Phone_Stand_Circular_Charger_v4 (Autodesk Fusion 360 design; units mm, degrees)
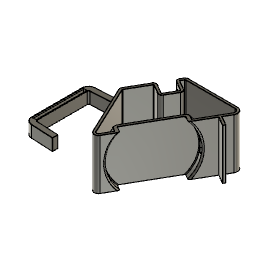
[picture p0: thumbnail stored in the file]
sketch "Sketch1" plane through (0, 0, 0) normal (0, 1, 0) x axis (1, 0, 0)
  line L1 (-76.7719, -132.9728) -> (-6.9282, -12)
  line L2 (120, 0) -> (0, 0)
  line L3 (-120.3527, -62.762) -> (-87.3932, -132.5355)
  line L4 (-13.8564, 0) -> (-83.7158, 0)
  line L5 (-31.1769, -36) -> (-25.1147, -39.5)
  line L6 (-82.0429, -122.1025) -> (-32.5429, -36.366)
  line L7 (-75.6147, -126.9686) -> (-81.6769, -123.4686)
  line L8 (-76.7719, -132.9728) -> (-74.8827, -129.7006)
  line L9 (-6.9282, -12) -> (-22.3827, -38.7679)
  line L10 (-0.1423, -30.2465) -> (-13.1327, -22.7465)
  line L11 (-1.8923, -33.2776) -> (-0.1423, -30.2465)
  line L12 (-14.8827, -25.7776) -> (-1.8923, -33.2776)
  line L13 (-88.0459, -2.5) -> (-120.1618, -58.1264)
  line L14 (-75.9216, -19.5) -> (-88.9119, -12)
  line L15 (-84.5555, -36.4545) -> (-75.5555, -20.866)
  line L16 (-98.9119, -29.3205) -> (-85.9216, -36.8205)
  line L17 (-120.1618, -58.1264) -> (-104.376, -30.7846)
  line L18 (-88.0459, -2.5) -> (-90.376, -6.5359)
  line L19 (-9.9593, -10.25) -> (-24.6638, -35.7189)
  line L20 (-13.8564, -3.5) -> (-83.7158, -3.5)
  line L21 (-85.0148, -4.25) -> (-87.345, -8.2859)
  line L22 (-74.1716, -16.4689) -> (-87.1619, -8.9689)
  line L23 (-81.5244, -38.2045) -> (-72.5244, -22.616)
  line L24 (-100.6619, -32.3516) -> (-87.6716, -39.8516)
  line L25 (-117.1307, -59.8764) -> (-101.345, -32.5346)
  line L26 (-117.188, -61.267) -> (-84.2285, -131.0406)
  line L27 (-79.803, -131.2228) -> (-78.6638, -129.2497)
  line L28 (-78.6638, -129.2497) -> (-83.4269, -126.4997)
  line L29 (-85.074, -120.3525) -> (-35.574, -34.616)
  line L30 (-29.4269, -32.9689) -> (-24.6638, -35.7189)
  line L31 (-24.6638, -35.7189) -> (-78.6638, -129.2497)
  arc A1 centre (-13.8564, -8) radius 8 clockwise from (-13.8564, 0) to (-6.9282, -12)
  arc A2 centre (-81.968, -129.9728) radius 6 clockwise from (-76.7719, -132.9728) to (-87.3932, -132.5355)
  arc A3 centre (-76.6147, -128.7006) radius 2 clockwise from (-75.6147, -126.9686) to (-74.8827, -129.7006)
  arc A4 centre (-24.1147, -37.7679) radius 2 clockwise from (-22.3827, -38.7679) to (-25.1147, -39.5)
  arc A5 centre (-81.1769, -122.6025) radius 1 clockwise from (-81.6769, -123.4686) to (-82.0429, -122.1025)
  arc A6 centre (-31.6769, -36.866) radius 1 clockwise from (-32.5429, -36.366) to (-31.1769, -36)
  arc A7 centre (-115.8317, -60.6264) radius 5 clockwise from (-120.3527, -62.762) to (-120.1618, -58.1264)
  arc A8 centre (-83.7158, -5) radius 5 clockwise from (-88.0459, -2.5) to (-83.7158, 0)
  arc A9 centre (-86.9119, -8.5359) radius 4 clockwise from (-88.9119, -12) to (-90.376, -6.5359)
  arc A10 centre (-100.9119, -32.7846) radius 4 clockwise from (-104.376, -30.7846) to (-98.9119, -29.3205)
  arc A11 centre (-85.4216, -35.9545) radius 1 clockwise from (-84.5555, -36.4545) to (-85.9216, -36.8205)
  arc A12 centre (-76.4216, -20.366) radius 1 clockwise from (-75.9216, -19.5) to (-75.5555, -20.866)
  arc A13 centre (-13.8564, -8) radius 4.5 clockwise from (-13.8564, -3.5) to (-9.9593, -10.25)
  arc A14 centre (-83.7158, -5) radius 1.5 clockwise from (-85.0148, -4.25) to (-83.7158, -3.5)
  arc A15 centre (-86.9119, -8.5359) radius 0.5 clockwise from (-87.1619, -8.9689) to (-87.345, -8.2859)
  arc A16 centre (-76.4216, -20.366) radius 4.5 clockwise from (-74.1716, -16.4689) to (-72.5244, -22.616)
  arc A17 centre (-85.4216, -35.9545) radius 4.5 clockwise from (-81.5244, -38.2045) to (-87.6716, -39.8516)
  arc A18 centre (-100.9119, -32.7846) radius 0.5 clockwise from (-101.345, -32.5346) to (-100.6619, -32.3516)
  arc A19 centre (-115.8317, -60.6264) radius 1.5 clockwise from (-117.188, -61.267) to (-117.1307, -59.8764)
  arc A20 centre (-81.968, -129.9728) radius 2.5 clockwise from (-79.803, -131.2228) to (-84.2285, -131.0406)
  arc A21 centre (-81.1769, -122.6025) radius 4.5 clockwise from (-83.4269, -126.4997) to (-85.074, -120.3525)
  arc A22 centre (-31.6769, -36.866) radius 4.5 clockwise from (-35.574, -34.616) to (-29.4269, -32.9689)
  point P1 (0, 0)
  point P2 (0, 0)
  point P6 (0, 0)
  point P7 (-23.3827, -40.5)
  point P5 (-150, 0)
  point P3 (-82.5, -142.8942)
  point P22 (-13.1327, -22.7465)
  point P9 (-82.5429, -122.9686)
  point P8 (-32.0429, -35.5)
  point P25 (-14.8827, -25.7776)
  point P38 (-92.376, -10)
  point P83 (-57.2929, -79.2343)
  point P23 (-0.1423, -30.2465)
  point P24 (-1.8923, -33.2776)
  horizontal L2
  coincident P1 P2
  coincident P1 P6
  parallel L2 L4
  coincident L1 P7
  perpendicular L1 L5
  perpendicular L5 L6
  perpendicular L1 L7
  coincident P5 L3
  coincident P5 L4
  coincident P2 L1
  coincident P6 L4
  tangent L1 A1
  tangent L4 A1
  coincident P3 L3
  coincident P3 L1
  tangent L3 A2
  tangent L1 A2
  tangent L7 A3
  tangent L8 A3
  parallel L1 L8
  coincident P7 L5
  coincident P7 L9
  tangent L5 A4
  tangent L9 A4
  coincident L9 P22
  perpendicular L9 L10
  perpendicular L10 L11
  parallel L10 L12
  coincident P9 L6
  coincident P9 L7
  tangent L6 A5
  tangent L7 A5
  coincident P8 L5
  coincident P8 L6
  tangent L5 A6
  tangent L6 A6
  coincident L1 P25
  parallel L1 L13
  tangent L13 A7
  tangent L3 A7
  tangent L4 A8
  tangent L13 A8
  coincident L13 P38
  perpendicular L13 L14
  perpendicular L14 L15
  perpendicular L13 L16
  coincident P38 L18
  coincident P38 L14
  tangent L18 A9
  tangent L14 A9
  tangent L16 A10
  tangent L17 A10
  parallel L13 L17
  tangent L16 A11
  tangent L15 A11
  tangent L14 A12
  tangent L15 A12
  equal A11 A12
  midpoint L6 P83
  dimension "d34_1" angle L1 L2 = 120
  dimension "d35_1" distance P2 P3 = 165
  dimension "d36_1" distance P5 P6 = 150
  dimension "d37_1" distance P7 P8 = 10
  dimension "d38_1" distance P6 P7 = 40.5
  dimension "d39_1" distance P8 P9 = 101
  dimension "d41_1" radius A1 = 8
  dimension "d42_1" radius A2 = 6
  dimension "d43_1" radius A3 = 2
  dimension "d44_1" radius A4 = 2
  dimension "d45_1" distance P23 P24 = 3.5
  dimension "d46_1" distance P22 P23 = 15
  dimension "d47_1" distance L5 L12 = 17
  dimension "d48_1" radius A5 = 1
  dimension "d49_1" radius A6 = 1
  dimension "d71_1" distance L1 L13 = 75
  dimension "d72_1" radius A7 = 5
  dimension "d73_1" radius A8 = 5
  dimension "d74_1" distance L14 L16 = 20
  dimension "d75_1" distance L13 L15 = 20
  dimension "d76_1" distance P2 P38 = 10
  dimension "d77_1" radius A9 = 4
  dimension "d78_1" radius A10 = 4
  dimension "d79_1" radius A11 = 1
  dimension "d80_1" = 3.5
extrude "Extrude1" new body sketch "Sketch1" profile of L1 L3 L4 L5 L7 A1 A2 L8 A3 L9 A4 L10 L11 L12 L13 A7 A8 L14 L15 L16 L17 L18 A9 A10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 along normal blind 72 named "d51_1"
work_plane "WorkPlane2"
sketch "Sketch9" plane through (-58.3067, 36, 68.0585) normal (0, -1, 0) x axis (1, 0, 0)
  line L1 (27.1298, -32.0585) -> (33.192, -28.5585)
  line L2 (-23.7362, 54.044) -> (25.7638, -31.6925)
  line L3 (28.8798, -35.0896) -> (33.6429, -32.3396)
  line L4 (-26.7673, 52.294) -> (22.7327, -33.4425)
  line L5 (-20.3571, 61.1911) -> (-25.1202, 58.4411)
  line L6 (-17.308, 58.91) -> (-23.3702, 55.41)
  line L7 (35.924, -29.2906) -> (-16.576, 61.6421)
  line L8 (9.674, 16.1757) -> (1.0138, 11.1757)
  line L9 (-2.0173, 9.4257) -> (1.0138, 11.1757)
  line L10 (-18.6071, 58.16) -> (-20.3571, 61.1911)
  line L11 (33.6429, -32.3396) -> (31.8929, -29.3085)
  arc A1 centre (34.192, -30.2906) radius 2 clockwise from (33.192, -28.5585) to (35.924, -29.2906)
  arc A2 centre (26.6298, -31.1925) radius 1 clockwise from (27.1298, -32.0585) to (25.7638, -31.6925)
  arc A3 centre (26.6298, -31.1925) radius 4.5 clockwise from (28.8798, -35.0896) to (22.7327, -33.4425)
  arc A4 centre (-22.8702, 54.544) radius 4.5 clockwise from (-26.7673, 52.294) to (-25.1202, 58.4411)
  arc A5 centre (-22.8702, 54.544) radius 1 clockwise from (-23.7362, 54.044) to (-23.3702, 55.41)
  arc A6 centre (-18.308, 60.6421) radius 2 clockwise from (-16.576, 61.6421) to (-17.308, 58.91)
  point P31 (-16.576, 61.6421)
  point P33 (-16.576, 61.6421)
  point P5 (35.924, -29.2906)
  point P34 (35.924, -29.2906)
  point P2 (1.0138, 11.1757)
  point P35 (1.0138, 11.1757)
  point P36 (9.674, 16.1757)
  point P37 (-2.0173, 9.4257)
  point P24 (-20.3571, 61.1911)
  point P38 (-20.3571, 61.1911)
  point P39 (-18.6071, 58.16)
  point P40 (31.8929, -29.3085)
  point P13 (33.6429, -32.3396)
  point P41 (33.6429, -32.3396)
  coincident P31 P33
  coincident P5 P34
  coincident P2 P35
  midpoint L7 P36
  midpoint L4 P37
  coincident P24 P38
  coincident L6 P39
  perpendicular L6 L10
  coincident L1 P40
  coincident P13 P41
  perpendicular L3 L11
revolve "Revolve1" sketch "Sketch9" AlongAngle 360
revolve "Revolve2" sketch "Sketch9" AlongAngle 360
split "Split3"
split "Split4"
work_plane "WorkPlane3" RotateAngle 0
sketch "Sketch2" plane through (-23.3827, 0, 40.5) normal (-0.5, 0, 0.866) x axis (0, 1, 0)
  line L1 (0, 2) -> (0, 9)
  line L2 (72, 2) -> (0, 2)
  line L3 (72, 9) -> (72, 2)
  line L4 (0, 9) -> (72, 9)
  line L5 (36, 9) -> (36, 2)
  line L6 (41, 1.8) -> (31, 1.8)
  line L7 (41, 9.3) -> (41, 1.8)
  line L8 (31, 9.3) -> (41, 9.3)
  line L9 (31, 1.8) -> (31, 9.3)
  line L10 (0, 0) -> (72, 0)
  arc A1 centre (41, 5.55) radius 3.75 clockwise from (41, 9.3) to (41, 1.8)
  arc A2 centre (31, 5.55) radius 3.75 clockwise from (31, 1.8) to (31, 9.3)
  point P6 (36, 2)
  point P7 (36, 9)
  point P12 (41, 5.55)
  point P14 (31, 5.55)
  point P8 (31, 1.8)
  point P9 (41, 1.8)
  point P11 (31, 9.3)
  midpoint L2 P6
  midpoint L4 P7
  horizontal L6
  vertical L7
  horizontal L8
  vertical L9
  midpoint L7 P12
  midpoint L9 P14
  dimension "d53_1" distance P8 P9 = 10
  dimension "d54_1" distance P8 P11 = 7.5
  dimension "d55_1" distance L5 L7 = 5
  dimension "d81_1" distance L6 L10 = 1.8
extrude "Extrude2" cut sketch "Sketch2" profile of L2 L4 L5 L6 L7 L8 L9 A1 A2 against normal blind 25 named "d56_1" and along normal blind 4.796
combine "Combine1"
fillet "Fillet1" radius 3.139 named "d58_1"
fillet "Fillet2" radius 0.5 named "d59_1"
fillet "Fillet3" radius 0.2
sketch "Sketch5" plane through (-27.4241, 0, 47.5) normal (-0.5, 0, 0.866) x axis (0, -1, 0)
  line L1 (0, -71) -> (-72, -71)
  line L2 (-72, -56) -> (0, -56)
  line L3 (-72, -71.5) -> (0, -71.5)
  line L4 (-36, -71.5) -> (-36, -56)
  line L5 (-46, -70.75) -> (-26, -70.75)
  line L6 (-46, -56.75) -> (-46, -70.75)
  line L7 (-26, -56.75) -> (-46, -56.75)
  line L8 (-26, -70.75) -> (-26, -56.75)
  line L9 (-46, -56.75) -> (-26, -70.75)
  line L10 (-26, -56.75) -> (-46, -70.75)
  line L11 (0, -56) -> (0, -71)
  line L12 (-72, -71) -> (-72, -56)
  point P8 (-36, -56)
  point P9 (-36, -71.5)
  point P10 (-36, -63.75)
  point P15 (-36, -63.75)
  point P13 (-46, -56.75)
  point P14 (-26, -56.75)
  point P12 (-46, -70.75)
  midpoint L2 P8
  midpoint L3 P9
  midpoint L4 P10
  horizontal L5
  perpendicular L5 L6
  parallel L5 L7
  parallel L6 L8
  coincident L9 P15
  coincident L10 P15
  coincident P10 P15
  dimension "d87_1" distance P13 P14 = 20
  dimension "d88_1" distance P12 P13 = 14
position "Position1"
sketch "Sketch1" plane through (0, 0, 0) normal (1, 0, 0) x axis (0, 1, 0)
  line L1 (39.1563, 42.5) -> (37.5, 10.8953)
  line L2 (35.5027, 9) -> (0, 9)
  line L3 (35.5027, 1) -> (0, 1)
  line L4 (47.1454, 42.0813) -> (45.489, 10.4766)
  line L5 (47.1454, 42.0813) -> (39.1563, 42.5)
  line L6 (2.3566, 1) -> (0, 1)
  line L7 (0, 1) -> (0, 9)
  line L8 (36.15, 7) -> (0, 7)
  line L9 (36.15, 3.2) -> (36.15, 7)
  line L10 (0, 3.2) -> (36.15, 3.2)
  line L11 (0, 7) -> (0, 3.2)
  line L12 (39.1344, 42.0813) -> (47.1454, 42.0813)
  arc A1 centre (35.5027, 11) radius 2 clockwise from (37.5, 10.8953) to (35.5027, 9)
  arc A2 centre (35.5027, 11) radius 10 clockwise from (45.489, 10.4766) to (35.5027, 1)
  point P12 (2.3566, 1)
  point P1 (0, 0)
  point P3 (0, 9)
  point P13 (0, 7)
  point P17 (39.1344, 42.0813)
  point P16 (0, 3.2)
  point P15 (36.15, 3.2)
  point P5 (37.5, 10.8953)
  point P2 (39.1563, 42.5)
  tangent L2 A1
  tangent L1 A1
  coincident L3 P12
  horizontal L2
  vertical P1 P3
  horizontal L8
  vertical L9
  horizontal L10
  vertical L11
  coincident L7 P13
  coincident L1 P17
  horizontal L12
  dimension "d112" radius A1 = 2
  dimension "d113" = 8
  dimension "d116" distance P13 P16 = 3.8
  dimension "d117" distance P15 P16 = 36.15
  dimension "d119" distance P1 P5 = 37.5
  dimension "d120" angle L1 L2 = 93
  dimension "d122" distance P2 L2 = 33.5
  dimension "d123" distance P1 L2 = 9
  dimension "d124" distance P1 L8 = 7
extrude "Extrude1" new body sketch "Sketch1" profile of L1 L2 A1 A2 L4 L3 L6 L7 L8 L9 L10 L11 L12 along normal blind 17
extrude "Extrude2" cut sketch "Sketch1" profile of L7 L8 L9 L10 L11 along normal blind 15.6
chamfer "Chamfer1" distance 0.963
mirror "Mirror1"
combine "Combine1"
fillet "Fillet1" radius 0.3
chamfer "Chamfer2" distance 0.3
sketch "Sketch10" plane through (0, 0, 0) normal (0, 1, 0) x axis (1, 0, 0)
  line L1 (-98.9119, -29.3205) -> (-85.9216, -36.8205)
  line L2 (-81.9837, -16) -> (-91.9837, -33.3205)
  line L3 (-75.9216, -19.5) -> (-88.9119, -12)
  line L4 (-85.0148, -14.25) -> (-95.0148, -31.5705)
  line L5 (-84.5555, -36.4545) -> (-75.5555, -20.866)
  point P4 (-91.9837, -33.3205)
  point P8 (-95.0148, -31.5705)
  point P9 (-85.0148, -14.25)
  coincident L1 P4
  coincident L1 P8
  coincident L3 P9
  perpendicular L2 L3
  perpendicular L3 L4
  dimension "d155" distance L2 L5 = 8
  dimension "d156" distance L2 L4 = 3.5
extrude "Extrude8" sketch "Sketch10" profile of L1 L2 L3 L4 blind -10 from offset -10
chamfer "Chamfer6" distance 3
chamfer "Chamfer5" distance 0.3 distance 0.3
align "Align1"
align "Align1"
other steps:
create_component "CreateComponent2"
create_component "CreateComponent3"
named bodies: "Bracket"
